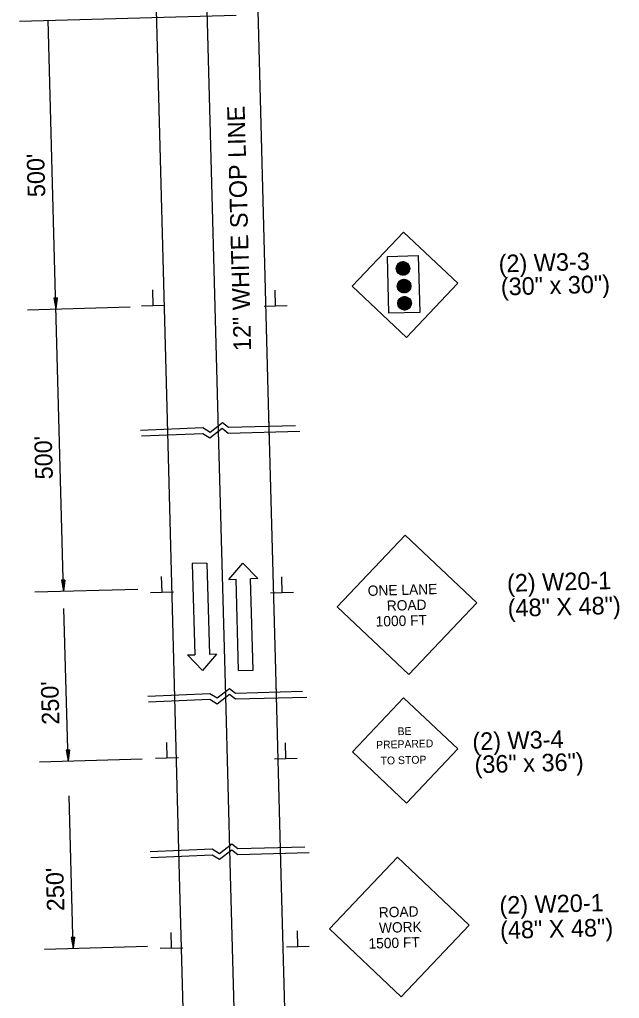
# Model space of a CAD drawing. Extents: x 1926836 to 1933254, y 596317 to 604524.
# Drawn here: x 1930961.5 to 1931166.8, y 596651.4 to 596986.4 of the extents above; entities that cross this region are included whole.
import ezdxf

# ---------------------------------------------------------------- set-up
doc = ezdxf.new("R2010")
doc.units = 0
doc.layers.add('Default', color=7, linetype='Continuous')
doc.layers.add('R_MOT', color=7, linetype='Continuous')

msp = doc.modelspace()

# ---------------------------------------------------------------- linework, layer by layer
at = {"layer": 'Default'}
for p, q in [((1931029.72, 596841.35), (1931025.43, 597001.21)), ((1931047.1, 596841.81), (1931042.81, 597001.68)), ((1931012.35, 596840.88), (1931008.05, 597000.74)), ((1930961.53, 596985.89), (1931035.64, 596987.88)), ((1930973.97, 596887.34), (1930971.32, 596986.14)), ((1931092.9, 596913.66), (1931075.38, 596895.13)), ((1931111.45, 596896.16), (1931092.9, 596913.66)), ((1931090.4, 596901.18), (1931092.63, 596903.53)), ((1931090.4, 596901.33), (1931092.48, 596903.52)), ((1931090.41, 596901.04), (1931092.77, 596903.54)), ((1931090.42, 596900.91), (1931092.91, 596903.53)), ((1931090.42, 596901.49), (1931092.32, 596903.5)), ((1931090.44, 596900.78), (1931093.03, 596903.52)), ((1931090.45, 596901.67), (1931092.15, 596903.46)), ((1931090.47, 596900.66), (1931093.15, 596903.5)), ((1931090.5, 596900.55), (1931093.27, 596903.47)), ((1931090.5, 596901.87), (1931091.95, 596903.4)), ((1931090.53, 596900.44), (1931093.38, 596903.44)), ((1931090.57, 596900.33), (1931093.49, 596903.41)), ((1931090.58, 596902.1), (1931091.72, 596903.31)), ((1931090.62, 596900.23), (1931093.59, 596903.37)), ((1931090.66, 596900.13), (1931093.69, 596903.33)), ((1931090.71, 596900.04), (1931093.79, 596903.28)), ((1931090.74, 596902.42), (1931091.41, 596903.13)), ((1931090.77, 596899.95), (1931093.88, 596903.23)), ((1931090.83, 596899.86), (1931093.97, 596903.18)), ((1931090.89, 596899.78), (1931094.05, 596903.12)), ((1931090.95, 596899.7), (1931094.14, 596903.06)), ((1931091.02, 596899.63), (1931094.22, 596903)), ((1931091.09, 596899.55), (1931094.29, 596902.93)), ((1931091.16, 596899.48), (1931094.37, 596902.86)), ((1931091.24, 596899.42), (1931094.44, 596902.79)), ((1931091.32, 596899.35), (1931094.5, 596902.71)), ((1931091.4, 596899.29), (1931094.57, 596902.63)), ((1931091.49, 596899.24), (1931094.63, 596902.55)), ((1931091.58, 596899.18), (1931094.69, 596902.47)), ((1931091.67, 596899.13), (1931094.74, 596902.38)), ((1931091.77, 596899.09), (1931094.79, 596902.28)), ((1931091.86, 596899.05), (1931094.84, 596902.19)), ((1931091.97, 596899.01), (1931094.89, 596902.09)), ((1931092.08, 596898.97), (1931094.93, 596901.98)), ((1931092.19, 596898.94), (1931094.96, 596901.87)), ((1931092.3, 596898.92), (1931094.99, 596901.76)), ((1931092.42, 596898.9), (1931095.02, 596901.64)), ((1931092.55, 596898.89), (1931095.04, 596901.51)), ((1931092.68, 596898.88), (1931095.05, 596901.38)), ((1931092.83, 596898.88), (1931095.06, 596901.24)), ((1931092.98, 596898.89), (1931095.05, 596901.09)), ((1931093.14, 596898.92), (1931095.04, 596900.92)), ((1931093.31, 596898.95), (1931095.01, 596900.75)), ((1931093.51, 596899.01), (1931094.96, 596900.55)), ((1931090.78, 596894.98), (1931093.15, 596897.48)), ((1931090.78, 596895.12), (1931093.01, 596897.48)), ((1931090.78, 596895.27), (1931092.86, 596897.47)), ((1931090.79, 596895.44), (1931092.7, 596897.45)), ((1931090.8, 596894.85), (1931093.28, 596897.48)), ((1931090.82, 596894.72), (1931093.41, 596897.46)), ((1931090.82, 596895.61), (1931092.52, 596897.41)), ((1931090.84, 596894.6), (1931093.53, 596897.44)), ((1931090.87, 596894.49), (1931093.65, 596897.42)), ((1931090.87, 596895.81), (1931092.32, 596897.35)), ((1931090.91, 596894.38), (1931093.76, 596897.39)), ((1931090.95, 596894.28), (1931093.87, 596897.35)), ((1931090.95, 596896.05), (1931092.09, 596897.25)), ((1931090.99, 596894.17), (1931093.97, 596897.32)), ((1931091.04, 596894.08), (1931094.07, 596897.27)), ((1931091.09, 596893.98), (1931094.16, 596897.23)), ((1931091.12, 596896.37), (1931091.78, 596897.07)), ((1931091.14, 596893.89), (1931094.26, 596897.18)), ((1931091.2, 596893.81), (1931094.34, 596897.12)), ((1931091.26, 596893.73), (1931094.43, 596897.07)), ((1931091.33, 596893.65), (1931094.51, 596897.01)), ((1931093.74, 596899.11), (1931094.88, 596900.31)), ((1931094.05, 596899.29), (1931094.71, 596899.99)), ((1931007.21, 596888.53), (1931007.07, 596893.87)), ((1931049.14, 596888.4), (1931049, 596893.73)), ((1931093.93, 596877.61), (1931075.38, 596895.13)), ((1931091.4, 596893.57), (1931094.59, 596896.94)), ((1931091.47, 596893.5), (1931094.67, 596896.88)), ((1931091.54, 596893.43), (1931094.74, 596896.81)), ((1931091.62, 596893.36), (1931094.81, 596896.74)), ((1931091.7, 596893.3), (1931094.88, 596896.66)), ((1931091.78, 596893.24), (1931094.94, 596896.58)), ((1931091.86, 596893.18), (1931095.01, 596896.5)), ((1931091.95, 596893.13), (1931095.06, 596896.41)), ((1931092.05, 596893.08), (1931095.12, 596896.32)), ((1931092.14, 596893.03), (1931095.17, 596896.23)), ((1931092.24, 596892.99), (1931095.22, 596896.13)), ((1931092.34, 596892.95), (1931095.26, 596896.03)), ((1931092.45, 596892.92), (1931095.3, 596895.93)), ((1931092.56, 596892.89), (1931095.34, 596895.82)), ((1931092.68, 596892.86), (1931095.37, 596895.7)), ((1931092.8, 596892.84), (1931095.39, 596895.58)), ((1931092.93, 596892.83), (1931095.41, 596895.45)), ((1931093.06, 596892.83), (1931095.43, 596895.32)), ((1931093.2, 596892.83), (1931095.43, 596895.18)), ((1931093.35, 596892.84), (1931095.43, 596895.03)), ((1931093.51, 596892.86), (1931095.42, 596894.87)), ((1931093.69, 596892.9), (1931095.39, 596894.69)), ((1931093.89, 596892.96), (1931095.34, 596894.49)), ((1931111.45, 596896.16), (1931093.93, 596877.61)), ((1931094.12, 596893.06), (1931095.25, 596894.25)), ((1931094.43, 596893.24), (1931095.09, 596893.93)), ((1930974.43, 596891.1), (1930973.3, 596891.07)), ((1930973.3, 596891.07), (1930973.97, 596887.34)), ((1930973.4, 596891.08), (1930973.95, 596887.97)), ((1930973.49, 596891.08), (1930973.93, 596888.61)), ((1930973.59, 596891.08), (1930973.92, 596889.23)), ((1930973.68, 596891.08), (1930973.9, 596889.87)), ((1930973.78, 596891.09), (1930973.88, 596890.5)), ((1930973.95, 596891.09), (1930973.88, 596890.5)), ((1930974.05, 596891.09), (1930973.9, 596889.87)), ((1930974.15, 596891.1), (1930973.92, 596889.23)), ((1930974.24, 596891.1), (1930973.93, 596888.61)), ((1930974.34, 596891.1), (1930973.95, 596887.97)), ((1930974.43, 596891.1), (1930973.97, 596887.34)), ((1931090.93, 596889.32), (1931093.08, 596891.59)), ((1931090.94, 596889.17), (1931093.23, 596891.6)), ((1931090.94, 596889.04), (1931093.37, 596891.59)), ((1931090.94, 596889.48), (1931092.93, 596891.57)), ((1931090.96, 596888.91), (1931093.5, 596891.58)), ((1931090.96, 596889.65), (1931092.76, 596891.54)), ((1931090.98, 596888.78), (1931093.62, 596891.57)), ((1931091, 596889.84), (1931092.57, 596891.49)), ((1931091.01, 596888.67), (1931093.74, 596891.55)), ((1931091.05, 596888.55), (1931093.85, 596891.52)), ((1931091.07, 596890.05), (1931092.36, 596891.41)), ((1931091.08, 596888.45), (1931093.96, 596891.49)), ((1931091.12, 596888.34), (1931094.07, 596891.45)), ((1931091.17, 596888.24), (1931094.17, 596891.41)), ((1931091.19, 596890.32), (1931092.1, 596891.28)), ((1931091.22, 596888.15), (1931094.27, 596891.37)), ((1931091.27, 596888.06), (1931094.36, 596891.32)), ((1931091.33, 596887.97), (1931094.45, 596891.27)), ((1931091.39, 596887.89), (1931094.54, 596891.21)), ((1931091.45, 596887.8), (1931094.63, 596891.15)), ((1931091.52, 596887.73), (1931094.71, 596891.09)), ((1931091.58, 596887.65), (1931094.78, 596891.03)), ((1931091.66, 596887.58), (1931094.86, 596890.96)), ((1931091.73, 596887.51), (1931094.93, 596890.89)), ((1931091.81, 596887.45), (1931095, 596890.82)), ((1931091.89, 596887.39), (1931095.07, 596890.74)), ((1931091.97, 596887.33), (1931095.13, 596890.66)), ((1931092.06, 596887.27), (1931095.19, 596890.57)), ((1931092.15, 596887.22), (1931095.25, 596890.49)), ((1931092.25, 596887.17), (1931095.3, 596890.39)), ((1931092.34, 596887.13), (1931095.35, 596890.3)), ((1930964.18, 596887.08), (1930999.38, 596888.02)), ((1930976.56, 596790.72), (1930973.94, 596888.18)), ((1931011.11, 596888.52), (1931003.29, 596888.31)), ((1931053.04, 596888.39), (1931045.21, 596888.18)), ((1931092.55, 596887.05), (1931095.44, 596890.1)), ((1931092.66, 596887.02), (1931095.48, 596889.99)), ((1931092.77, 596886.99), (1931095.51, 596889.88)), ((1931092.89, 596886.97), (1931095.54, 596889.76)), ((1931093.01, 596886.95), (1931095.56, 596889.64)), ((1931093.14, 596886.94), (1931095.58, 596889.51)), ((1931093.28, 596886.94), (1931095.59, 596889.37)), ((1931093.42, 596886.94), (1931095.59, 596889.23)), ((1931093.58, 596886.96), (1931095.58, 596889.07)), ((1931093.75, 596886.99), (1931095.56, 596888.91)), ((1931093.93, 596887.04), (1931095.53, 596888.72)), ((1931094.14, 596887.11), (1931095.46, 596888.51)), ((1931094.4, 596887.23), (1931095.35, 596888.24)), ((1931094.84, 596887.56), (1931095.06, 596887.78)), ((1931049.43, 596755.24), (1931046.86, 596850.98)), ((1931014.67, 596754.31), (1931012.35, 596840.88)), ((1931032.05, 596754.77), (1931029.72, 596841.35)), ((1931093.44, 596809.96), (1931070.18, 596785.43)), ((1931117.97, 596786.71), (1931093.44, 596809.96)), ((1930977.02, 596794.49), (1930975.9, 596794.46)), ((1930975.9, 596794.46), (1930976.56, 596790.72)), ((1930975.99, 596794.46), (1930976.54, 596791.35)), ((1930976.09, 596794.46), (1930976.53, 596791.99)), ((1930976.18, 596794.46), (1930976.51, 596792.62)), ((1930976.28, 596794.47), (1930976.49, 596793.25)), ((1930976.37, 596794.47), (1930976.48, 596793.88)), ((1930976.55, 596794.47), (1930976.48, 596793.88)), ((1930976.64, 596794.48), (1930976.49, 596793.25)), ((1930976.74, 596794.48), (1930976.51, 596792.62)), ((1930976.83, 596794.48), (1930976.53, 596791.99)), ((1930976.93, 596794.48), (1930976.54, 596791.35)), ((1930977.02, 596794.49), (1930976.56, 596790.72)), ((1931010.27, 596790.44), (1931010.12, 596795.78)), ((1931051.35, 596790.28), (1931051.21, 596795.62)), ((1930966.77, 596790.46), (1931001.97, 596791.4)), ((1931014.16, 596790.43), (1931006.34, 596790.22)), ((1931055.25, 596790.27), (1931047.43, 596790.06)), ((1931117.97, 596786.71), (1931094.72, 596762.19)), ((1930978.12, 596732.64), (1930976.72, 596784.81)), ((1931094.72, 596762.19), (1931070.18, 596785.43)), ((1931051.08, 596693.74), (1931049.08, 596768.06)), ((1931016.3, 596693.48), (1931014.67, 596754.31)), ((1931033.69, 596693.61), (1931032.05, 596754.77)), ((1931092.93, 596754.27), (1931075.41, 596735.73)), ((1931111.48, 596736.76), (1931092.93, 596754.27)), ((1930978.58, 596736.41), (1930977.46, 596736.37)), ((1930977.46, 596736.37), (1930978.12, 596732.64)), ((1930977.55, 596736.38), (1930978.1, 596733.27)), ((1930977.65, 596736.38), (1930978.09, 596733.91)), ((1930977.74, 596736.38), (1930978.07, 596734.54)), ((1930977.84, 596736.39), (1930978.05, 596735.17)), ((1930977.93, 596736.39), (1930978.04, 596735.8)), ((1930978.11, 596736.39), (1930978.04, 596735.8)), ((1930978.2, 596736.39), (1930978.05, 596735.17)), ((1930978.3, 596736.4), (1930978.07, 596734.54)), ((1930978.39, 596736.4), (1930978.09, 596733.91)), ((1930978.49, 596736.4), (1930978.1, 596733.27)), ((1930978.58, 596736.41), (1930978.12, 596732.64)), ((1931012, 596733.67), (1931011.86, 596739)), ((1931052.67, 596733.49), (1931052.52, 596738.83)), ((1931111.48, 596736.76), (1931093.96, 596718.21)), ((1930968.33, 596732.38), (1931003.53, 596733.32)), ((1931015.9, 596733.66), (1931008.08, 596733.45)), ((1931056.56, 596733.48), (1931048.74, 596733.27)), ((1931093.96, 596718.21), (1931075.41, 596735.73)), ((1930979.84, 596668.5), (1930978.44, 596720.67)), ((1931090.84, 596699.71), (1931067.59, 596675.17)), ((1931115.38, 596676.45), (1931090.84, 596699.71)), ((1931017.97, 596631.53), (1931016.3, 596693.48)), ((1931035.33, 596632.46), (1931033.69, 596693.61)), ((1931052.7, 596633.38), (1931051.08, 596693.74)), ((1931115.38, 596676.45), (1931092.12, 596651.93)), ((1931013.52, 596668.61), (1931013.37, 596673.95)), ((1931056.78, 596669.1), (1931056.64, 596674.44)), ((1931092.12, 596651.93), (1931067.59, 596675.17)), ((1930970.05, 596668.24), (1931005.25, 596669.19)), ((1930980.3, 596672.27), (1930979.18, 596672.24)), ((1930979.18, 596672.24), (1930979.84, 596668.5)), ((1930979.27, 596672.24), (1930979.82, 596669.13)), ((1930979.37, 596672.24), (1930979.81, 596669.77)), ((1930979.46, 596672.24), (1930979.79, 596670.4)), ((1930979.56, 596672.25), (1930979.77, 596671.03)), ((1930979.65, 596672.25), (1930979.76, 596671.66)), ((1930979.83, 596672.25), (1930979.76, 596671.66)), ((1930979.92, 596672.26), (1930979.77, 596671.03)), ((1930980.02, 596672.26), (1930979.79, 596670.4)), ((1930980.11, 596672.26), (1930979.81, 596669.77)), ((1930980.21, 596672.27), (1930979.82, 596669.13)), ((1930980.3, 596672.27), (1930979.84, 596668.5)), ((1931017.41, 596668.6), (1931009.59, 596668.39)), ((1931060.67, 596669.09), (1931052.85, 596668.88))]:
    msp.add_line(p, q, dxfattribs=at)
msp.add_lwpolyline([(1931087.41, 596905.3), (1931097.93, 596905.59), (1931098.45, 596886.17), (1931087.93, 596885.89)], close=True, dxfattribs=at)
for points in [[(1931002.94, 596845.87), (1931024.23, 596846.76), (1931026.69, 596845.2), (1931030.93, 596848.48), (1931032.98, 596846.87), (1931055.94, 596847.49)], [(1931003.19, 596843.88), (1931024.2, 596844.76), (1931026.66, 596843.21), (1931030.9, 596846.49), (1931032.95, 596844.87), (1931057.4, 596845.53)], [(1931005.38, 596754.85), (1931026.68, 596755.75), (1931029.13, 596754.19), (1931033.38, 596757.47), (1931035.42, 596755.86), (1931058.38, 596756.47)], [(1931005.63, 596752.87), (1931026.65, 596753.75), (1931029.11, 596752.19), (1931033.35, 596755.47), (1931035.39, 596753.86), (1931059.84, 596754.51)], [(1931006.18, 596701.63), (1931027.47, 596702.53), (1931029.93, 596700.97), (1931034.18, 596704.25), (1931036.22, 596702.64), (1931059.18, 596703.25)], [(1931006.43, 596699.64), (1931027.44, 596700.53), (1931029.9, 596698.97), (1931034.14, 596702.25), (1931036.19, 596700.64), (1931060.64, 596701.29)]]:
    msp.add_lwpolyline(points, dxfattribs=at)
for centre in [(1931092.73, 596901.21), (1931093.1, 596895.15), (1931093.26, 596889.27)]:
    msp.add_circle(centre, 2.33, dxfattribs=at)
at = {"layer": 'R_MOT'}
for p, q in [((1931025.62, 596800.31), (1931020.62, 596800.18)), ((1931020.62, 596800.18), (1931021.46, 596768.97)), ((1931025.62, 596800.31), (1931026.46, 596769.1)), ((1931033.1, 596794.77), (1931037.95, 596800.38)), ((1931037.95, 596800.38), (1931043.1, 596795.04)), ((1931033.1, 596794.77), (1931035.6, 596794.84)), ((1931036.44, 596763.62), (1931035.6, 596794.84)), ((1931043.1, 596795.04), (1931040.6, 596794.97)), ((1931041.44, 596763.76), (1931040.6, 596794.97)), ((1931018.96, 596768.9), (1931021.46, 596768.97)), ((1931024.11, 596763.55), (1931018.96, 596768.9)), ((1931028.96, 596769.17), (1931024.11, 596763.55)), ((1931028.96, 596769.17), (1931026.46, 596769.1)), ((1931036.44, 596763.62), (1931041.44, 596763.76))]:
    msp.add_line(p, q, dxfattribs=at)

# ---------------------------------------------------------------- texts
at = {"layer": 'Default'}
for s, height, rotation, p in [('12" WHITE STOP LINE', 6, 91.5377, (1931040.78, 596873.01)), ("500'", 6, 91.5377, (1930970.33, 596925.69)), ('(2) W3-3', 6, 1.5377, (1931125.53, 596899.83)), ('(30" x 30")', 6, 1.5377, (1931126.28, 596891.95)), ("500'", 6, 91.5377, (1930972.92, 596829.07)), ('(2) W20-1', 6, 1.5377, (1931128.39, 596790.51)), ('ONE LANE', 3.521, 1.5381, (1931080.7, 596789.11)), ('ROAD', 3.52, 1.5377, (1931087.22, 596784.01)), ('(48" X 48")', 6, 1.5377, (1931128.62, 596781.95)), ('1000 FT', 3.522, 1.5383, (1931083.42, 596778.62)), ("250'", 6, 91.5377, (1930975.18, 596745.1)), ('BE', 2.658, 1.6381, (1931090.92, 596741.44)), ('(2) W3-4', 6, 1.5377, (1931116.54, 596736.29)), ('PREPARED', 2.658, 1.638, (1931083.58, 596736.8)), ('TO STOP', 2.675, 1.5383, (1931085.08, 596731.36)), ('(36" x 36")', 6, 1.5377, (1931117.28, 596728.41)), ("250'", 6, 91.5377, (1930976.89, 596681.28)), ('(2) W20-1', 6, 1.5377, (1931125.8, 596680.25)), ('ROAD', 3.521, 1.5381, (1931084.49, 596679.03)), ('WORK', 3.52, 1.5377, (1931084.56, 596673.75)), ('(48" X 48")', 6, 1.5377, (1931126.03, 596671.69)), ('1500 FT', 3.522, 1.5383, (1931080.96, 596668.37))]:
    msp.add_text(s, height=height, rotation=rotation, dxfattribs=at).set_placement(p)

doc.saveas('drawing.dxf')
